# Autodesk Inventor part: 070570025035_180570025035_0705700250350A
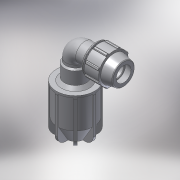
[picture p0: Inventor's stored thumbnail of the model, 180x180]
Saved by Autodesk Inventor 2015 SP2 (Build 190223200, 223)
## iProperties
Created: 2017-02
Part Number: 070570025035_180570025035_0705700250350A
Material: PVC-Piping
Description: PLASSON PLASS4 90° ELBOW 27-35*25
Document SubType Name: Modeling
Designer: KIM
Mass: 92.6774 g
Surface Area: 199.44 cm^2
Volume: 66.1981 cm^3
Density: 1.4 g/cm^3
Appearance: Smooth - White
Author: KIM
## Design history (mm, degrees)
derived "070570.ipt"
feature "Solid1::070570.ipt"
tag "TaggingFeature1"
body "Solid1"
other parameters: "d2" = 25, "d4" = 11.57143, "d5" = 16.2, "d7" = 54, "d8" = 34.23797, "d9" = 11.57143, "d11" = 2.31429, "d12" = 43.2, "d13" = 120 deg, "d14" = 37.5, "d15" = 12 deg, "d16" = 48.6, "d18" = 1.25, "d19" = 35 deg, "d20" = 17.5 deg, "d21" = 50.22, "d23" = 0, "d25" = 360 deg, "d27" = 1.08, "d42" = 24.3, "d43" = 1.62, "d46" = 0.75, "d53" = 0.5, "d67" = 2.7, "d70" = 22.5, "d71" = 58, "d73" = 81, "d74" = 90 deg, "d75" = 35, "d76" = 83, "d77" = 153, "d78" = 4.05, "d80" = 22.5, "d82" = 112, "d84" = 78.85, "d85" = 135 deg, "d86" = 4.15, "d88" = 112, "d89" = 4.15, "d90" = 135 deg, "d91" = 84, "d92" = 24.48, "d93" = 28, "d94" = 4.15, "d95" = 5.6, "d97" = 4.32, "d98" = 0, "d100" = 360 deg, "d102" = 91.3, "d103" = 16.6, "d104" = 6.64, "d105" = 0, "d107" = 16.2, "d108" = 0, "d109" = 0, "d_" = 25, "E_" = 54, "A_" = 81, "l_" = 58, "d_1" = 35, "E_1" = 83, "l_1" = 112, "A_1" = 153, "d106" = 34.23797
